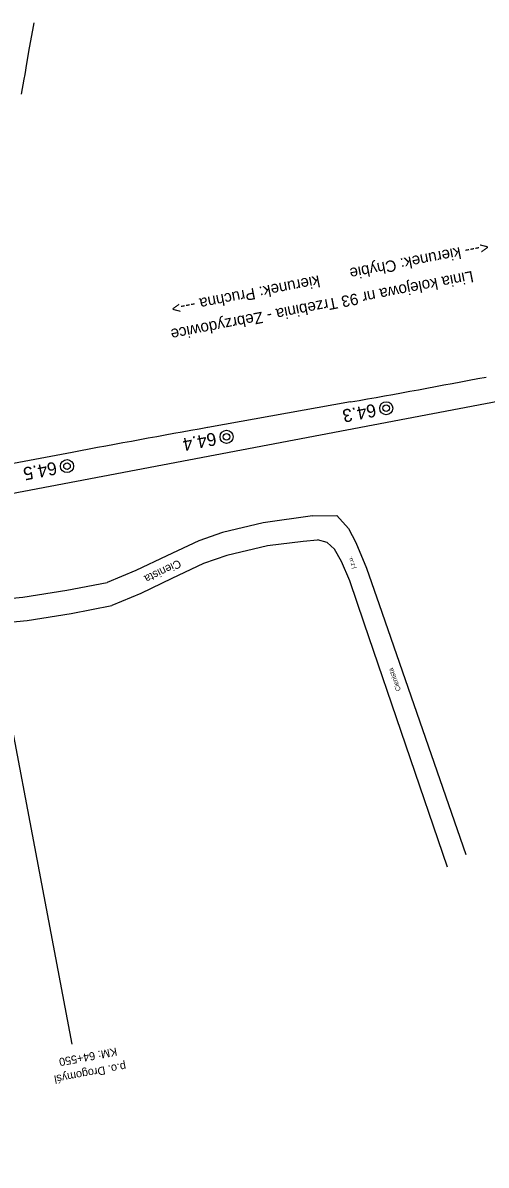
# Model space of a CAD drawing. Extents: x 6541740 to 6556805, y 5525233 to 5530361.
# Drawn here: x 6556457.6 to 6556529, y 5525917.2 to 5526093.4 of the extents above; entities that cross this region are included whole.
import ezdxf

# ---------------------------------------------------------------- set-up
doc = ezdxf.new("R2010")
doc.units = 0
for name, color, linetype in [('Default', 7, 'Continuous'), ('TOR_SCH-hektometry', 7, 'Continuous'), ('TOR_SCH-opisy dodatkowe', 7, 'Continuous'), ('TOR_SCH-opisy glowne', 7, 'Continuous'), ('TOR_SCH-przejazdy+drogi istniejace', 7, 'Continuous'), ('TOR_SCH-tory projektowane', 7, 'Continuous')]:
    doc.layers.add(name, color=color, linetype=linetype)

# ---------------------------------------------------------------- blocks, each defined once
blk = doc.blocks.new('4010_1')
at = {"layer": 'Default'}
for radius in [0.75, 0.375]:
    blk.add_circle((0, 0), radius, dxfattribs=at)

msp = doc.modelspace()

# ---------------------------------------------------------------- linework, layer by layer
at = {"layer": 'TOR_SCH-opisy glowne'}
msp.add_lwpolyline([(6556465.13, 5525935.87), (6556449.87, 5526016.63), (6556449.87, 5526016.63), (6556449.87, 5526016.63)], dxfattribs=at)
at = {"layer": 'TOR_SCH-przejazdy+drogi istniejace'}
for p, q in [((6556459.09, 5526092.28), (6556459.3, 5526093.42)), ((6556458.59, 5526089.59), (6556459.09, 5526092.28)), ((6556458.18, 5526087.17), (6556458.59, 5526089.59)), ((6556457.89, 5526085.44), (6556458.18, 5526087.17)), ((6556457.36, 5526082.42), (6556457.77, 5526084.72)), ((6556457.77, 5526084.72), (6556457.89, 5526085.44)), ((6556502.17, 5526017.37), (6556505.93, 5526017.41)), ((6556505.93, 5526017.41), (6556507.74, 5526015.45)), ((6556507.74, 5526015.45), (6556508.86, 5526013.27)), ((6556504.44, 5526013.29), (6556502.97, 5526013.67)), ((6556505.56, 5526012.22), (6556504.44, 5526013.29)), ((6556506.66, 5526010.33), (6556505.56, 5526012.22)), ((6556508.86, 5526013.27), (6556510.49, 5526009.29)), ((6556507.95, 5526007.35), (6556506.66, 5526010.33)), ((6556510.49, 5526009.29), (6556512.48, 5526003.7)), ((6556510.16, 5526000.82), (6556507.95, 5526007.35)), ((6556512.48, 5526003.7), (6556525.81, 5525965.13)), ((6556523.01, 5525963.19), (6556510.16, 5526000.82))]:
    msp.add_line(p, q, dxfattribs=at)
for points in [[(6556502.17, 5526017.37), (6556494.6, 5526016.28), (6556494.6, 5526016.28), (6556488.31, 5526014.79), (6556484.68, 5526013.55), (6556479.76, 5526011.23), (6556474.99, 5526008.95), (6556470.57, 5526007.08)], [(6556502.98, 5526013.61), (6556500.73, 5526013.41), (6556495.27, 5526012.73), (6556489.01, 5526011.25), (6556485.39, 5526010.02), (6556480.49, 5526007.7), (6556475.72, 5526005.42), (6556471.29, 5526003.55)], [(6556429.23, 5525989.04), (6556429.57, 5525990.16), (6556432.08, 5525996.72), (6556433.28, 5525998.41), (6556435.93, 5525999.45), (6556442.15, 5526001.91), (6556446.51, 5526003.97), (6556452.05, 5526004.3), (6556457.57, 5526004.84), (6556464.32, 5526005.92), (6556470.57, 5526007.08)], [(6556434.7, 5525995.11), (6556436.65, 5525995.88), (6556442.87, 5525998.34), (6556447.21, 5526000.39), (6556452.71, 5526000.72), (6556458.23, 5526001.25), (6556464.99, 5526002.34), (6556471.29, 5526003.55)]]:
    msp.add_lwpolyline(points, dxfattribs=at)
at = {"layer": 'TOR_SCH-tory projektowane'}
for p, q in [((6556735.03, 5526073.73), (6555909.41, 5525917.23)), ((6556508.05, 5526034.94), (6556486.04, 5526031)), ((6556465.14, 5526027.15), (6556381.1, 5526011.22))]:
    msp.add_line(p, q, dxfattribs=at)
for centre, start_param, end_param in [((6550392.46, 5558412.33), 3.139013, 3.141593), ((6562601.64, 5493653.62), 6.280606, 6.283185)]:
    msp.add_ellipse(centre, major_axis=(-6136.5, 32373.54), ratio=0.25, start_param=start_param, end_param=end_param, dxfattribs=at)

# ---------------------------------------------------------------- block references
at = {"layer": 'TOR_SCH-hektometry', "xscale": 1.345963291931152, "yscale": 1.345963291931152}
for p in [(6556513.56, 5526033.98), (6556488.95, 5526029.57), (6556464.36, 5526025.05)]:
    msp.add_blockref('4010_1', p, dxfattribs=at)

# ---------------------------------------------------------------- texts
at = {"layer": 'TOR_SCH-hektometry'}
for s, p in [('64.3', (6556511.79, 5526034.69)), ('64.4', (6556487.17, 5526030.28)), ('64.5', (6556462.59, 5526025.76))]:
    msp.add_text(s, height=2, rotation=190.7691, dxfattribs=at).set_placement(p)
at = {"layer": 'TOR_SCH-opisy dodatkowe'}
for s, height, rotation, p in [('<--- kierunek: Chybie', 1.75, 191.0012, (6556529.17, 5526059.69)), ('Linia kolejowa nr 93 Trzebinia - Zebrzydowice', 1.7499, 190.987, (6556526.82, 5526055.18)), ('kierunek: Pruchna --->', 1.75, 191.0012, (6556503.15, 5526054.49))]:
    msp.add_text(s, height=height, rotation=rotation, dxfattribs=at).set_placement(p)
at = {"layer": 'TOR_SCH-opisy glowne'}
for s, p in [('KM: 64+550', (6556471.95, 5525935.37)), ('p.o. Drogomyśl', (6556473.34, 5525933.09))]:
    msp.add_text(s, height=1.25, rotation=190.5522, dxfattribs=at).set_placement(p)
at = {"layer": 'TOR_SCH-przejazdy+drogi istniejace'}
for s, height, rotation, p in [('Cienista', 1.247, 205.5354, (6556481.58, 5526010.68)), ('j.z.u.', 0.667, 108.6577, (6556508.85, 5526009.34)), ('Cienista', 0.748, 110.1733, (6556515.83, 5525990.5))]:
    msp.add_text(s, height=height, rotation=rotation, dxfattribs=at).set_placement(p)

doc.saveas('drawing.dxf')
